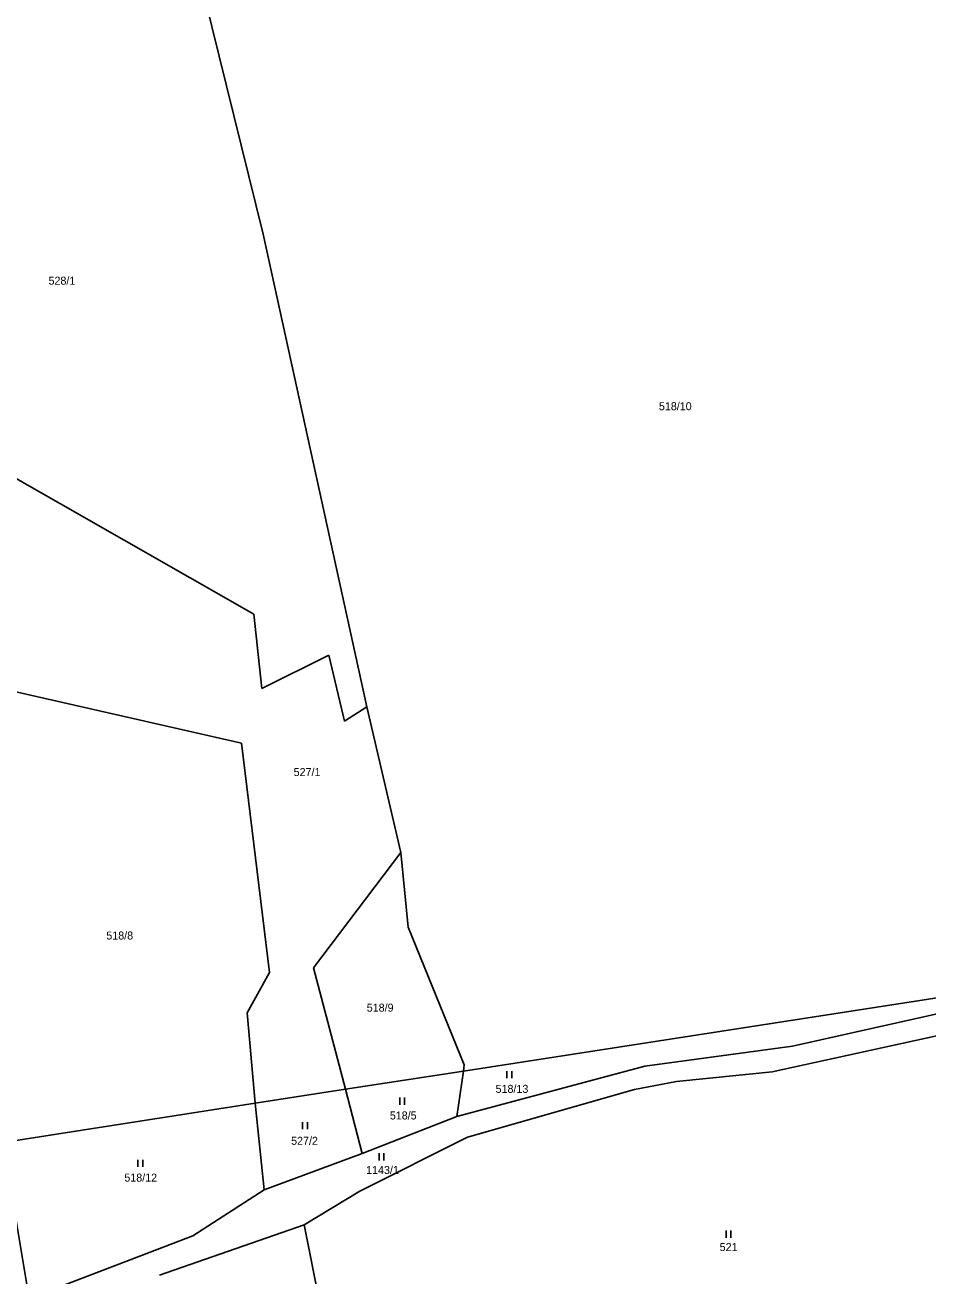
# Model space of a CAD drawing. Extents: x -765428 to -762163, y -1107632 to -1104975.
# Drawn here: x -764695.4 to -764503.8, y -1106034.3 to -1105768.8 of the extents above; entities that cross this region are included whole.
import ezdxf
from ezdxf.enums import TextEntityAlignment as Align

# ---------------------------------------------------------------- set-up
doc = ezdxf.new("R2010")
doc.units = 0
doc.header["$LTSCALE"] = 0.68
doc.layers.add('1', color=7, linetype='Continuous', lineweight=25)
doc.layers.add('3', color=7, linetype='Continuous', lineweight=25)
doc.layers.add('2', color=7, linetype='Continuous')

msp = doc.modelspace()

# ---------------------------------------------------------------- linework, layer by layer
at = {"layer": '1'}
for p, q in [((-764644.86, -1105813.22), (-764660.46, -1105749.98)), ((-764622.88, -1105913.61), (-764644.86, -1105813.22)), ((-764717.09, -1105853.88), (-764646.85, -1105893.94)), ((-764646.85, -1105893.94), (-764645.13, -1105909.73)), ((-764645.13, -1105909.73), (-764630.94, -1105902.67)), ((-764630.94, -1105902.67), (-764627.65, -1105916.65)), ((-764649.49, -1105921.33), (-764718.18, -1105905.68)), ((-764627.65, -1105916.65), (-764622.88, -1105913.61)), ((-764622.88, -1105913.61), (-764615.64, -1105944.54)), ((-764643.56, -1105970.07), (-764649.49, -1105921.33)), ((-764615.64, -1105944.54), (-764634.18, -1105969.07)), ((-764615.64, -1105944.54), (-764614.07, -1105960.45)), ((-764614.07, -1105960.45), (-764602.2, -1105989.68)), ((-764634.18, -1105969.07), (-764627.39, -1105994.86)), ((-764648.25, -1105978.62), (-764643.56, -1105970.07)), ((-764602.38, -1105990.99), (-764493.07, -1105974.05)), ((-764532.53, -1105985.7), (-764492, -1105976.6)), ((-764646.57, -1105997.81), (-764648.25, -1105978.62)), ((-764479.66, -1105978.64), (-764536.86, -1105991.14)), ((-764563.9, -1105989.93), (-764532.53, -1105985.7)), ((-764627.39, -1105994.86), (-764602.38, -1105990.99)), ((-764603.74, -1106000.67), (-764563.9, -1105989.93)), ((-764602.38, -1105990.99), (-764603.74, -1106000.67)), ((-764602.2, -1105989.68), (-764602.38, -1105990.99)), ((-764536.86, -1105991.14), (-764557.12, -1105993.19)), ((-764557.12, -1105993.19), (-764566.09, -1105994.92)), ((-764646.57, -1105997.81), (-764627.39, -1105994.86)), ((-764627.39, -1105994.86), (-764623.88, -1106008.49)), ((-764566.09, -1105994.92), (-764601.53, -1106005.04)), ((-764700.09, -1106006.14), (-764646.57, -1105997.81)), ((-764646.57, -1105997.81), (-764644.67, -1106016.24)), ((-764623.88, -1106008.49), (-764603.74, -1106000.67)), ((-764601.53, -1106005.04), (-764624.34, -1106016.52)), ((-764644.67, -1106016.24), (-764623.88, -1106008.49)), ((-764644.67, -1106016.24), (-764659.81, -1106025.95)), ((-764624.34, -1106016.52), (-764636.2, -1106023.64)), ((-764636.2, -1106023.64), (-764666.9, -1106034.32)), ((-764624.21, -1106083.66), (-764636.2, -1106023.64)), ((-764659.81, -1106025.95), (-764694.55, -1106039.31))]:
    msp.add_line(p, q, dxfattribs=at)
msp.add_lwpolyline([(-764713.46, -1105926.07), (-764700.09, -1106006.14), (-764694.55, -1106039.31)], dxfattribs=at)
at = {"layer": '3'}
for p, q in [((-764593.131, -1105992.48), (-764593.131, -1105990.98)), ((-764592.13, -1105992.48), (-764592.13, -1105990.98)), ((-764615.901, -1105998.13), (-764615.901, -1105996.63)), ((-764614.9, -1105998.13), (-764614.9, -1105996.63)), ((-764636.501, -1106003.36), (-764636.501, -1106001.86)), ((-764635.5, -1106003.36), (-764635.5, -1106001.86)), ((-764620.261, -1106009.95), (-764620.261, -1106008.45)), ((-764619.26, -1106009.95), (-764619.26, -1106008.45)), ((-764671.461, -1106011.35), (-764671.461, -1106009.85)), ((-764670.46, -1106011.35), (-764670.46, -1106009.85)), ((-764546.621, -1106026.38), (-764546.621, -1106024.88)), ((-764545.62, -1106026.38), (-764545.62, -1106024.88))]:
    msp.add_line(p, q, dxfattribs=at)

# ---------------------------------------------------------------- texts
at = {"layer": '2'}
for s, p in [('528/1', (-764687.6, -1105823.965)), ('518/10', (-764557.4, -1105850.625)), ('518/8', (-764675.33, -1105963.045)), ('518/9', (-764620.05, -1105978.365)), ('518/13', (-764592.07, -1105995.615)), ('518/5', (-764615.15, -1106001.265)), ('518/12', (-764670.87, -1106014.465))]:
    msp.add_text(s, height=1.7, dxfattribs=at).set_placement(p, align=Align.CENTER)
for s, p in [('527/1', (-764638.41, -1105928.325)), ('527/2', (-764638.95, -1106006.645)), ('1143/1', (-764623.03, -1106012.845)), ('521', (-764547.98, -1106029.215))]:
    msp.add_text(s, height=1.7, dxfattribs=at).set_placement(p)

doc.saveas('drawing.dxf')
